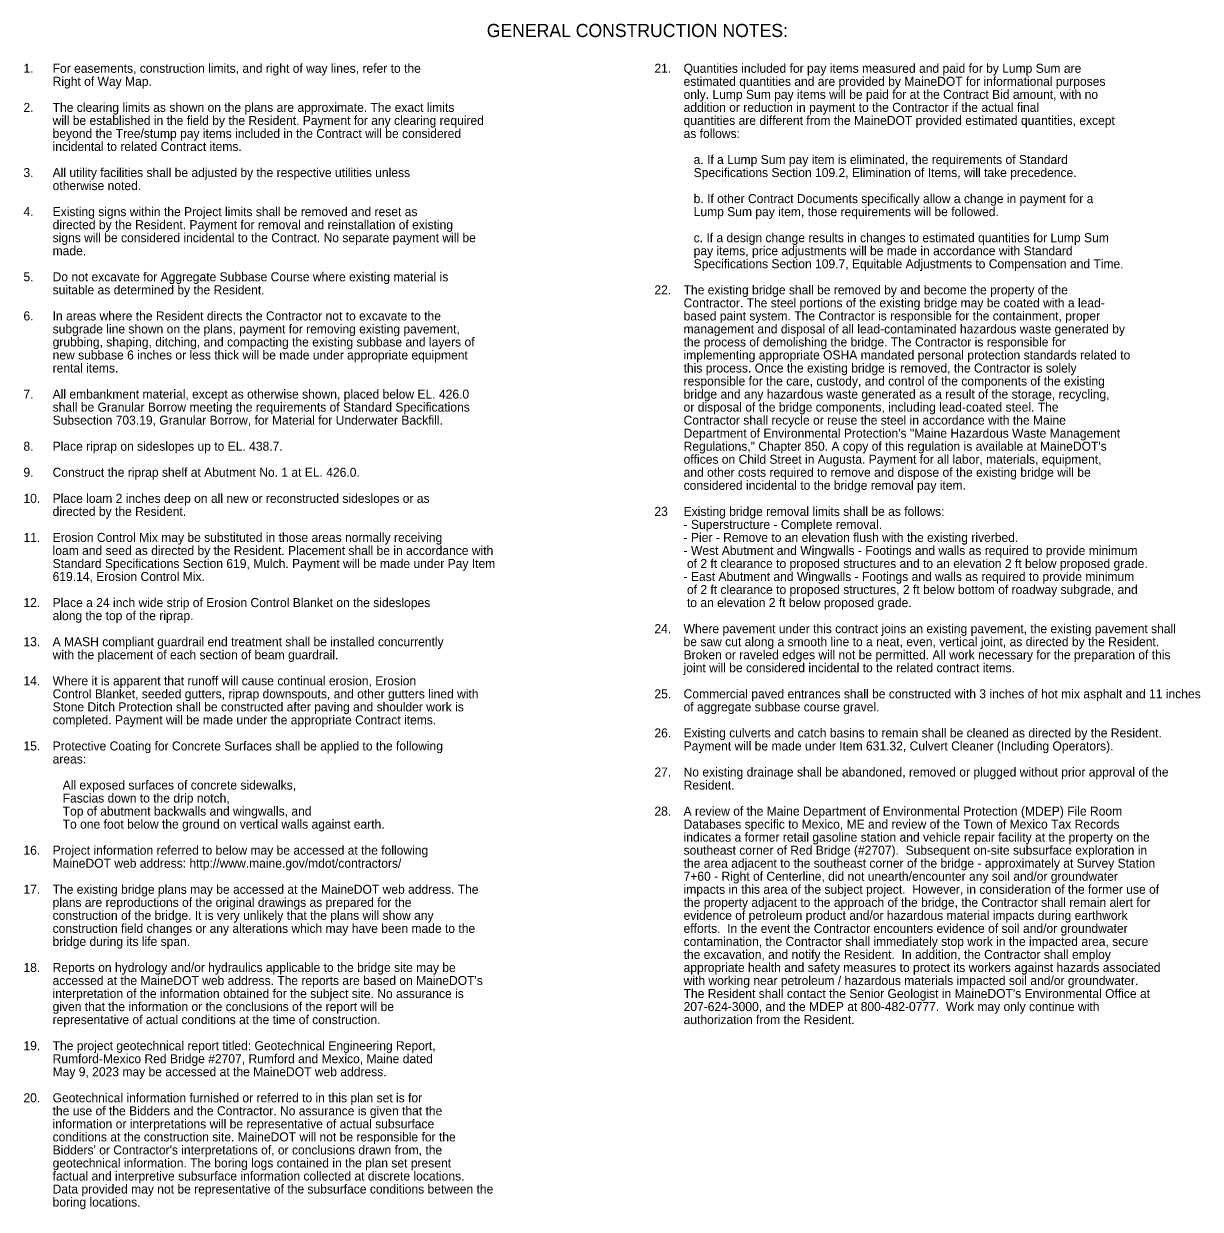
# Model space of a CAD drawing. Extents: x 1574687 to 1574845, y 466925 to 467022.
# Drawn here: x 1574687.3 to 1574765.6, y 466943.3 to 467022.2 of the extents above; entities that cross this region are included whole.
import ezdxf

# ---------------------------------------------------------------- set-up
doc = ezdxf.new("R2010")
doc.units = 0
doc.layers.add('H_V CONTROLS', color=7, linetype='Continuous')

msp = doc.modelspace()

# ---------------------------------------------------------------- texts
at = {"layer": 'H_V CONTROLS'}
for s, height, p in [('GENERAL CONSTRUCTION NOTES:', 0.875, (1574718.11, 467021.306)), ('1.', 0.6, (1574687.3, 467018.928)), ('For easements, construction limits, and right of way lines, refer to the', 0.6, (1574689.24, 467018.928)), ('21.', 0.6, (1574729.256, 467018.928)), ('Quantities included for pay items measured and paid for by Lump Sum are', 0.6, (1574731.196, 467018.928)), ('Right of Way Map.', 0.6, (1574689.24, 467018.061)), ('estimated quantities and are provided by MaineDOT for informational purposes', 0.6, (1574731.196, 467018.061)), ('only. Lump Sum pay items will be paid for at the Contract Bid amount, with no', 0.6, (1574731.196, 467017.194)), ('2.', 0.6, (1574687.3, 467016.328)), ('The clearing limits as shown on the plans are approximate. The exact limits', 0.6, (1574689.24, 467016.328)), ('addition or reduction in payment to the Contractor if the actual final', 0.6, (1574731.196, 467016.328)), ('will be established in the field by the Resident. Payment for any clearing required', 0.6, (1574689.24, 467015.461)), ('quantities are different from the MaineDOT provided estimated quantities, except', 0.6, (1574731.196, 467015.461)), ('beyond the Tree/stump pay items included in the Contract will be considered', 0.6, (1574689.24, 467014.594)), ('as follows:', 0.6, (1574731.196, 467014.594)), ('incidental to related Contract items.', 0.6, (1574689.24, 467013.727)), ('   a. If a Lump Sum pay item is eliminated, the requirements of Standard', 0.6, (1574731.196, 467012.86)), ('3.', 0.6, (1574687.3, 467011.993)), ('All utility facilities shall be adjusted by the respective utilities unless', 0.6, (1574689.24, 467011.993)), ('   Specifications Section 109.2, Elimination of Items, will take precedence.', 0.6, (1574731.196, 467011.993)), ('otherwise noted.', 0.6, (1574689.24, 467011.126)), ('   b. If other Contract Documents specifically allow a change in payment for a', 0.6, (1574731.196, 467010.259)), ('4.', 0.6, (1574687.3, 467009.392)), ('Existing signs within the Project limits shall be removed and reset as', 0.6, (1574689.24, 467009.392)), ('   Lump Sum pay item, those requirements will be followed.', 0.6, (1574731.196, 467009.392)), ('directed by the Resident. Payment for removal and reinstallation of existing', 0.6, (1574689.24, 467008.526)), ('signs will be considered incidental to the Contract. No separate payment will be', 0.6, (1574689.24, 467007.659)), ('   c. If a design change results in changes to estimated quantities for Lump Sum', 0.6, (1574731.196, 467007.659)), ('made.', 0.6, (1574689.24, 467006.792)), ('   pay items, price adjustments will be made in accordance with Standard', 0.6, (1574731.196, 467006.792)), ('   Specifications Section 109.7, Equitable Adjustments to Compensation and Time.', 0.6, (1574731.196, 467005.925)), ('5.', 0.6, (1574687.3, 467005.058)), ('Do not excavate for Aggregate Subbase Course where existing material is', 0.6, (1574689.24, 467005.058)), ('suitable as determined by the Resident.', 0.6, (1574689.24, 467004.191)), ('The existing bridge shall be removed by and become the property of the', 0.6, (1574731.196, 467004.191)), ('22.', 0.6, (1574729.256, 467004.191)), ('Contractor. The steel portions of the existing bridge may be coated with a lead-', 0.6, (1574731.196, 467003.324)), ('6.', 0.6, (1574687.3, 467002.457)), ('In areas where the Resident directs the Contractor not to excavate to the', 0.6, (1574689.24, 467002.457)), ('based paint system. The Contractor is responsible for the containment, proper', 0.6, (1574731.196, 467002.457)), ('subgrade line shown on the plans, payment for removing existing pavement,', 0.6, (1574689.24, 467001.59)), ('management and disposal of all lead-contaminated hazardous waste generated by', 0.6, (1574731.196, 467001.59)), ('grubbing, shaping, ditching, and compacting the existing subbase and layers of', 0.6, (1574689.24, 467000.723)), ('the process of demolishing the bridge. The Contractor is responsible for', 0.6, (1574731.196, 467000.723)), ('new subbase 6 inches or less thick will be made under appropriate equipment', 0.6, (1574689.24, 466999.857)), ('implementing appropriate OSHA mandated personal protection standards related to', 0.6, (1574731.196, 466999.857)), ('rental items.', 0.6, (1574689.24, 466998.99)), ('this process. Once the existing bridge is removed, the Contractor is solely', 0.6, (1574731.196, 466998.99)), ('responsible for the care, custody, and control of the components of the existing', 0.6, (1574731.196, 466998.123)), ('7.', 0.6, (1574687.3, 466997.256)), ('All embankment material, except as otherwise shown, placed below EL. 426.0', 0.6, (1574689.24, 466997.256)), ('bridge and any hazardous waste generated as a result of the storage, recycling,', 0.6, (1574731.196, 466997.256)), ('shall be Granular Borrow meeting the requirements of Standard Specifications', 0.6, (1574689.24, 466996.389)), ('or disposal of the bridge components, including lead-coated steel. The', 0.6, (1574731.196, 466996.389)), ('Subsection 703.19, Granular Borrow, for Material for Underwater Backfill.', 0.6, (1574689.24, 466995.522)), ('Contractor shall recycle or reuse the steel in accordance with the Maine', 0.6, (1574731.196, 466995.522)), ('Department of Environmental Protection\'s "Maine Hazardous Waste Management', 0.6, (1574731.196, 466994.655)), ('8.', 0.6, (1574687.3, 466993.788)), ('Place riprap on sideslopes up to EL. 438.7.', 0.6, (1574689.24, 466993.788)), ('Regulations," Chapter 850. A copy of this regulation is available at MaineDOT\'s', 0.6, (1574731.196, 466993.788)), ('offices on Child Street in Augusta. Payment for all labor, materials, equipment,', 0.6, (1574731.196, 466992.921)), ('9.', 0.6, (1574687.3, 466992.055)), ('Construct the riprap shelf at Abutment No. 1 at EL. 426.0.', 0.6, (1574689.24, 466992.055)), ('and other costs required to remove and dispose of the existing bridge will be', 0.6, (1574731.196, 466992.055)), ('considered incidental to the bridge removal pay item.', 0.6, (1574731.196, 466991.188)), ('10.', 0.6, (1574687.3, 466990.321)), ('Place loam 2 inches deep on all new or reconstructed sideslopes or as', 0.6, (1574689.24, 466990.321)), ('directed by the Resident.', 0.6, (1574689.24, 466989.454)), ('23', 0.6, (1574729.256, 466989.454)), ('Existing bridge removal limits shall be as follows:', 0.6, (1574731.196, 466989.454)), ('- Superstructure - Complete removal.', 0.6, (1574731.196, 466988.587)), ('11.', 0.6, (1574687.3, 466987.72)), ('Erosion Control Mix may be substituted in those areas normally receiving', 0.6, (1574689.24, 466987.72)), ('- Pier - Remove to an elevation flush with the existing riverbed.', 0.6, (1574731.196, 466987.72)), ('loam and seed as directed by the Resident. Placement shall be in accordance with', 0.6, (1574689.24, 466986.853)), ('- West Abutment and Wingwalls - Footings and walls as required to provide minimum', 0.6, (1574731.196, 466986.853)), ('Standard Specifications Section 619, Mulch. Payment will be made under Pay Item', 0.6, (1574689.24, 466985.986)), (' of 2 ft clearance to proposed structures and to an elevation 2 ft below proposed grade.', 0.6, (1574731.196, 466985.986)), ('619.14, Erosion Control Mix.', 0.6, (1574689.24, 466985.119)), ('- East Abutment and Wingwalls - Footings and walls as required to provide minimum', 0.6, (1574731.196, 466985.119)), (' of 2 ft clearance to proposed structures, 2 ft below bottom of roadway subgrade, and', 0.6, (1574731.196, 466984.253)), ('12.', 0.6, (1574687.3, 466983.386)), ('Place a 24 inch wide strip of Erosion Control Blanket on the sideslopes', 0.6, (1574689.24, 466983.386)), (' to an elevation 2 ft below proposed grade.', 0.6, (1574731.196, 466983.386)), ('along the top of the riprap.', 0.6, (1574689.24, 466982.519)), ('24.', 0.6, (1574729.256, 466981.652)), ('Where pavement under this contract joins an existing pavement, the existing pavement shall', 0.6, (1574731.196, 466981.652)), ('13.', 0.6, (1574687.3, 466980.785)), ('A MASH compliant guardrail end treatment shall be installed concurrently', 0.6, (1574689.24, 466980.785)), ('be saw cut along a smooth line to a neat, even, vertical joint, as directed by the Resident. ', 0.6, (1574731.196, 466980.785)), ('with the placement of each section of beam guardrail.', 0.6, (1574689.24, 466979.918)), ('Broken or raveled edges will not be permitted. All work necessary for the preparation of this', 0.6, (1574731.196, 466979.918)), ('joint will be considered incidental to the related contract items.', 0.6, (1574731.196, 466979.051)), ('Where it is apparent that runoff will cause continual erosion, Erosion', 0.6, (1574689.24, 466978.184)), ('14.', 0.6, (1574687.3, 466978.184)), ('Control Blanket, seeded gutters, riprap downspouts, and other gutters lined with', 0.6, (1574689.24, 466977.317)), ('25.', 0.6, (1574729.256, 466977.317)), ('Commercial paved entrances shall be constructed with 3 inches of hot mix asphalt and 11 inches', 0.6, (1574731.196, 466977.317)), ('Stone Ditch Protection shall be constructed after paving and shoulder work is', 0.6, (1574689.24, 466976.45)), ('of aggregate subbase course gravel.', 0.6, (1574731.196, 466976.45)), ('completed. Payment will be made under the appropriate Contract items.', 0.6, (1574689.24, 466975.584)), ('26.', 0.6, (1574729.256, 466974.717)), ('Existing culverts and catch basins to remain shall be cleaned as directed by the Resident.', 0.6, (1574731.196, 466974.717)), ('15.', 0.6, (1574687.3, 466973.85)), ('Protective Coating for Concrete Surfaces shall be applied to the following', 0.6, (1574689.24, 466973.85)), ('Payment will be made under Item 631.32, Culvert Cleaner (Including Operators).', 0.6, (1574731.196, 466973.85)), ('areas:', 0.6, (1574689.24, 466972.983)), ('27.', 0.6, (1574729.256, 466972.116)), ('No existing drainage shall be abandoned, removed or plugged without prior approval of the', 0.6, (1574731.196, 466972.116)), ('   All exposed surfaces of concrete sidewalks,', 0.6, (1574689.24, 466971.249)), ('Resident.', 0.6, (1574731.196, 466971.249)), ('   Fascias down to the drip notch,', 0.6, (1574689.24, 466970.382)), ('   Top of abutment backwalls and wingwalls, and', 0.6, (1574689.24, 466969.515)), ('28.', 0.6, (1574729.256, 466969.515)), ('A review of the Maine Department of Environmental Protection (MDEP) File Room ', 0.6, (1574731.196, 466969.515)), ('   To one foot below the ground on vertical walls against earth.', 0.6, (1574689.24, 466968.648)), ('Databases specific to Mexico, ME and review of the Town of Mexico Tax Records ', 0.6, (1574731.196, 466968.648)), ('indicates a former retail gasoline station and vehicle repair facility at the property on the ', 0.6, (1574731.196, 466967.782)), ('16.', 0.6, (1574687.3, 466966.915)), ('Project information referred to below may be accessed at the following', 0.6, (1574689.24, 466966.915)), ('southeast corner of Red Bridge (#2707).  Subsequent on-site subsurface exploration in ', 0.6, (1574731.196, 466966.915)), ('MaineDOT web address: http://www.maine.gov/mdot/contractors/', 0.6, (1574689.24, 466966.048)), ('the area adjacent to the southeast corner of the bridge - approximately at Survey Station ', 0.6, (1574731.196, 466966.048)), ('7+60 - Right of Centerline, did not unearth/encounter any soil and/or groundwater ', 0.6, (1574731.196, 466965.181)), ('17.', 0.6, (1574687.3, 466964.314)), ('The existing bridge plans may be accessed at the MaineDOT web address. The', 0.6, (1574689.24, 466964.314)), ('impacts in this area of the subject project.  However, in consideration of the former use of ', 0.6, (1574731.196, 466964.314)), ('plans are reproductions of the original drawings as prepared for the', 0.6, (1574689.24, 466963.447)), ('the property adjacent to the approach of the bridge, the Contractor shall remain alert for ', 0.6, (1574731.196, 466963.447)), ('construction of the bridge. It is very unlikely that the plans will show any', 0.6, (1574689.24, 466962.58)), ('evidence of petroleum product and/or hazardous material impacts during earthwork ', 0.6, (1574731.196, 466962.58)), ('construction field changes or any alterations which may have been made to the', 0.6, (1574689.24, 466961.713)), ('efforts.  In the event the Contractor encounters evidence of soil and/or groundwater ', 0.6, (1574731.196, 466961.713)), ('bridge during its life span.', 0.6, (1574689.24, 466960.846)), ('contamination, the Contractor shall immediately stop work in the impacted area, secure ', 0.6, (1574731.196, 466960.846)), ('the excavation, and notify the Resident.  In addition, the Contractor shall employ ', 0.6, (1574731.196, 466959.98)), ('18.', 0.6, (1574687.3, 466959.113)), ('Reports on hydrology and/or hydraulics applicable to the bridge site may be', 0.6, (1574689.24, 466959.113)), ('appropriate health and safety measures to protect its workers against hazards associated ', 0.6, (1574731.196, 466959.113)), ("accessed at the MaineDOT web address. The reports are based on MaineDOT's", 0.6, (1574689.24, 466958.246)), ('with working near petroleum / hazardous materials impacted soil and/or groundwater.  ', 0.6, (1574731.196, 466958.246)), ('interpretation of the information obtained for the subject site. No assurance is', 0.6, (1574689.24, 466957.379)), ("The Resident shall contact the Senior Geologist in MaineDOT's Environmental Office at ", 0.6, (1574731.196, 466957.379)), ('given that the information or the conclusions of the report will be', 0.6, (1574689.24, 466956.512)), ('207-624-3000, and the MDEP at 800-482-0777.  Work may only continue with ', 0.6, (1574731.196, 466956.512)), ('representative of actual conditions at the time of construction.', 0.6, (1574689.24, 466955.645)), ('authorization from the Resident. ', 0.6, (1574731.196, 466955.645)), ('19.', 0.6, (1574687.3, 466953.911)), ('The project geotechnical report titled: Geotechnical Engineering Report,', 0.6, (1574689.24, 466953.911)), ('Rumford-Mexico Red Bridge #2707, Rumford and Mexico, Maine dated', 0.6, (1574689.24, 466953.044)), ('May 9, 2023 may be accessed at the MaineDOT web address.', 0.6, (1574689.24, 466952.178)), ('20.', 0.6, (1574687.3, 466950.444)), ('Geotechnical information furnished or referred to in this plan set is for', 0.6, (1574689.24, 466950.444)), ('the use of the Bidders and the Contractor. No assurance is given that the', 0.6, (1574689.24, 466949.577)), ('information or interpretations will be representative of actual subsurface', 0.6, (1574689.24, 466948.71)), ('conditions at the construction site. MaineDOT will not be responsible for the', 0.6, (1574689.24, 466947.843)), ("Bidders' or Contractor's interpretations of, or conclusions drawn from, the", 0.6, (1574689.24, 466946.976)), ('geotechnical information. The boring logs contained in the plan set present', 0.6, (1574689.24, 466946.109)), ('factual and interpretive subsurface information collected at discrete locations.', 0.6, (1574689.24, 466945.242)), ('Data provided may not be representative of the subsurface conditions between the', 0.6, (1574689.24, 466944.375)), ('boring locations.', 0.6, (1574689.24, 466943.509))]:
    msp.add_text(s, height=height, dxfattribs=at).set_placement(p)

doc.saveas('drawing.dxf')
